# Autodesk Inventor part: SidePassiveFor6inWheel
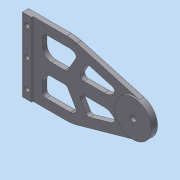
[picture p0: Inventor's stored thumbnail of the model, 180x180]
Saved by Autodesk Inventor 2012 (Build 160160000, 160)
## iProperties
Created: 2011-12
Part Number: SidePassiveFor6inWheel
Document SubType Name: Modeling
Designer: OSR
Density: 2.81 g/cm^3
Material: Aluminum-7075
Mass: 84.9466 g
Surface Area: 161.166 cm^2
Volume: 30.2301 cm^3
Author: OSR
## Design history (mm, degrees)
sketch "Sketch1"
  geometry: L1 (0, 0)-(0, 76.2); L2 (0, 76.2)-(44.45, 76.2); L3 (54.781, 74.772)-(119.868, 56.436); L4 (119.868, 19.764)-(54.781, 1.428); L5 (44.45, 0)-(0, 0); L6 (114.702, 38.1)-(0, 38.1); A1 r 19.05 centre (114.702, 38.1) between (119.868, 19.764) and (119.868, 56.436); A2 r 38.1 centre (44.45, 38.1) between (54.781, 74.772) and (44.45, 76.2); A3 r 38.1 centre (44.45, 38.1) between (44.45, 0) and (54.781, 1.428)
  constraints: 12 end point, 6 point on circle, 6 tangent, 3 centre point, 2 parallel, 1 concentric, 1 horizontal, 1 midpoint, 1 perpendicular, 1 vertical
  dimensions: "d0" = 76.2 distance of L1.start L1.end; "d1" = 114.7022 distance of L6.start L6.end; "d2" = 38.1 radius of A2; "d3" = 44.45 distance of L1.end L2.end; "d4" = 38.1 diameter of A1
extrude "Extrusion1" new body sketch "Sketch1" distance "d5" = 6.35; taper "d6" = 0 deg
sketch "Sketch2"
  geometry: L1 (0, 0)-(0, 76.2) reference; L2 (44.45, 0)-(0, 0) reference; L3 (119.868, 19.764)-(54.781, 1.428) reference; L4 (54.781, 74.772)-(119.868, 56.436) reference; L5 (0, 76.2)-(44.45, 76.2) reference; L6 (9.525, 76.2)-(9.525, 0); A1 r 38.1 centre (44.45, 38.1) between (44.45, 0) and (54.781, 1.428) reference; A2 r 19.05 centre (114.702, 38.1) between (119.868, 19.764) and (119.868, 56.436) reference; A3 r 38.1 centre (44.45, 38.1) between (54.781, 74.772) and (44.45, 76.2) reference; 1 further point
  constraints: 2 end point, 2 point on line, 1 coincident, 1 perpendicular, 3 other
  dimensions: "d7" = 9.525 distance between parallel lines of L1 L6
extrude "Extrusion2" cut sketch "Sketch2" distance "d8" = 1.5875; taper "d9" = 0 deg
sketch "Sketch3"
  geometry: L1 (0, 76.2)-(9.525, 76.2) reference; L2 (9.525, 0)-(0, 0) reference; L3 (4.763, 0)-(4.762, 76.2); 3 further points
  constraints: 3 midpoint, 2 end point, 2 point on line
  dimensions: "d10" = 9.525 distance from line of L2 point (4.763, 9.525); "d11" = 9.525 distance from line of L1 point (4.762, 66.675)
hole "Hole1" sketch "Sketch3" at (4.763, 9.525), (4.762, 66.675), (4.763, 38.1) diameter "d12" = 4.8514; stored, may be unused: countersink angle "d16" = 82 deg, drill point angle "d18" = 118 deg; dims "d13" = 19.05, "d14" = 9.525, "d15" = 6.35, "d17" = 25.4
sketch "Sketch4"
  geometry: A1 r 19.05 centre (-114.702, 38.1) between (-119.868, 56.436) and (-119.868, 19.764) reference; 1 further point
  constraints: 1 coincident
hole "Hole2" sketch "Sketch4" at (-114.702, 38.1) diameter "d19" = 6.35; stored, may be unused: countersink angle "d23" = 82 deg, drill point angle "d25" = 118 deg; dims "d20" = 19.05, "d21" = 12.7, "d22" = 3.175, "d24" = 25.4
sketch "Sketch5"
  geometry: L1 (54.781, 74.772)-(119.868, 56.436) reference; L2 (9.525, 76.2)-(44.45, 76.2) reference; L3 (9.525, 76.2)-(9.525, 0) reference; L4 (28.575, 44.45)-(42.25, 44.45); L5 (45.55, 46.355)-(53.589, 60.279); L6 (51.322, 65.851)-(48.905, 66.532); L7 (47.872, 66.675)-(22.86, 66.675); L8 (19.05, 62.865)-(19.05, 53.975); L9 (62.048, 44.45)-(83.553, 44.45); L10 (91.273, 54.596)-(68.35, 61.054); L11 (64.017, 59.292)-(58.748, 50.165); L12 (9.525, 38.1)-(114.702, 38.1); L13 (19.05, 13.335)-(19.05, 22.225); L14 (47.872, 9.525)-(22.86, 9.525); L15 (51.322, 10.349)-(48.905, 9.668); L16 (45.55, 29.845)-(53.589, 15.921); L17 (28.575, 31.75)-(42.25, 31.75); L18 (64.017, 16.908)-(58.748, 26.035); L19 (91.273, 21.604)-(68.35, 15.146); L20 (62.048, 31.75)-(83.553, 31.75); A1 r 19.05 centre (114.702, 38.1) between (119.868, 56.436) and (119.868, 19.764) reference; A2 r 3.81 centre (22.86, 62.865) between (22.86, 66.675) and (19.05, 62.865); A3 r 9.525 centre (28.575, 53.975) between (19.05, 53.975) and (28.575, 44.45); A4 r 3.81 centre (42.25, 48.26) between (42.25, 44.45) and (45.55, 46.355); A5 r 23.812 centre (114.702, 38.1) between (93.187, 27.895) and (93.059, 28.169); A6 r 3.81 centre (50.289, 62.184) between (53.589, 60.279) and (51.322, 65.851); A7 r 3.81 centre (47.872, 62.865) between (48.905, 66.532) and (47.872, 66.675); A8 r 3.81 centre (62.048, 48.26) between (58.748, 50.165) and (62.048, 44.45); A9 r 3.81 centre (67.317, 57.387) between (68.35, 61.054) and (64.017, 59.292); A10 r 12.7 centre (83.553, 57.15) between (83.553, 44.45) and (93.852, 49.719); A11 r 3.81 centre (90.24, 50.929) between (93.852, 49.719) and (91.273, 54.596); A12 r 3.81 centre (22.86, 13.335) between (19.05, 13.335) and (22.86, 9.525); A13 r 3.81 centre (47.872, 13.335) between (47.872, 9.525) and (48.905, 9.668); A14 r 3.81 centre (50.289, 14.016) between (51.322, 10.349) and (53.589, 15.921); A15 r 3.81 centre (42.25, 27.94) between (45.55, 29.845) and (42.25, 31.75); A16 r 9.525 centre (28.575, 22.225) between (28.575, 31.75) and (19.05, 22.225); A17 r 3.81 centre (62.048, 27.94) between (62.048, 31.75) and (58.748, 26.035); A18 r 3.81 centre (67.317, 18.813) between (64.017, 16.908) and (68.35, 15.146); A19 r 3.81 centre (90.24, 25.271) between (91.273, 21.604) and (93.852, 26.481); A20 r 12.7 centre (83.553, 19.05) between (93.852, 26.481) and (83.553, 31.75); 6 further points
  constraints: 39 point on circle, 34 end point, 26 symmetric about line, 19 centre point, 18 tangent, 6 point on line, 5 parallel, 3 equal radius, 2 collinear, 1 coincident, 1 midpoint, 1 perpendicular, 9 other
  dimensions: "d29" = 9.525 distance between parallel lines of L2 L7; "d32" = 9.525 distance between parallel lines of L1 L10; "d35" = 9.525 distance between parallel lines of L5 L11; "d37" = 120 deg angle of L5 L4; "d39" = 25.4 distance of point (19.05, 44.45) point (44.45, 44.45); "d48" = 4.7625 radial gap between concentric circles of A1 A5; "d49" = 6.35 distance between parallel lines of L12 L9; "d50" = 9.525 distance between parallel lines of L3 L8; "d51" = 3.81 radius of A2; "d52" = 3.81 radius of A6; "d53" = 9.525 radius of A3; "d54" = 3.81 radius of A4; "d55" = 12.7 radius of A10; "d56" = 3.81 radius of A11
extrude "Extrusion3" cut sketch "Sketch5" stored distance "d44" = 25.4; taper "d45" = 0 deg
body "Solid1"
other parameters: "d34" = 4.7625
